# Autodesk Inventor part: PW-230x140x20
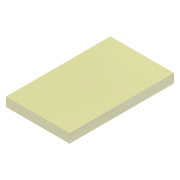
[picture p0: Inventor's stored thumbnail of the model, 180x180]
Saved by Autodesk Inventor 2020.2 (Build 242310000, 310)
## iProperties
Created: 2015-11
Part Number: PW-230x140x20
Material: Ogólny
Document SubType Name: Modeling
Designer: F.Stasiak
Density: 1 g/cm^3
Appearance: Przezroczysty - żółty
Catalog Web Link: www.expertbooks.pl
Manager: www.cadconsulting.pl
Company: Fabian Stasiak CAD Consulting
Author: F.Stasiak
Subject: Zbiór ćwiczeń. Autodesk Inventor 2020. Kurs Professional
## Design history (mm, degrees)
sketch "Szkic1"
  geometry: L1 (-70, 115)-(70, 115); L2 (70, 115)-(70, -115); L3 (70, -115)-(-70, -115); L4 (-70, -115)-(-70, 115); L5 (-70, 115)-(70, -115); L6 (70, 115)-(-70, -115); 1 further point
  constraints: 12 end point, 2 midpoint, 2 parallel, 1 horizontal, 1 perpendicular
  dimensions: "d0" = 140 distance of L2.end L3.end; "d1" = 230 distance of L1.end L2.end
extrude "Wyciągnięcie proste1" new body sketch "Szkic1" distance "d2" = 20; taper "d3" = 0 deg
node "Bryła1"
